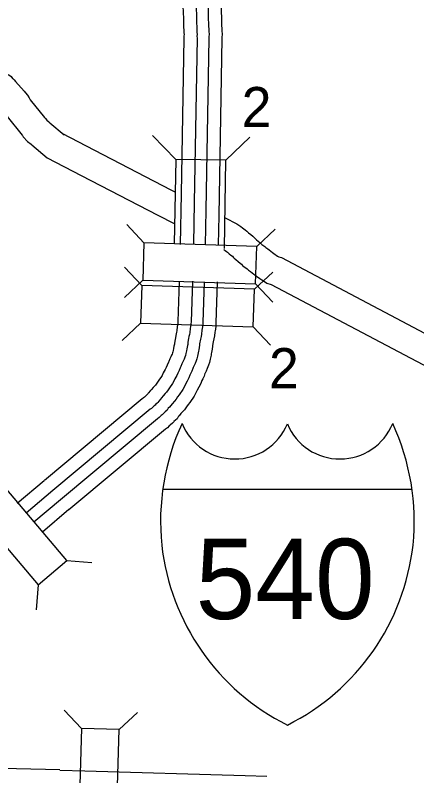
# Model space of a CAD drawing. Extents: x 535214 to 694517, y 381272 to 484355.
# Drawn here: x 544123 to 546236, y 450462 to 454464 of the extents above; entities that cross this region are included whole.
import ezdxf

# ---------------------------------------------------------------- set-up
doc = ezdxf.new("R2010")
doc.units = 0
for name, color, linetype in [('Level 10', 7, 'Continuous'), ('Level 19', 7, 'Continuous'), ('Level 20', 7, 'Continuous'), ('Level 23', 7, 'Continuous')]:
    doc.layers.add(name, color=color, linetype=linetype)

msp = doc.modelspace()

# ---------------------------------------------------------------- linework, layer by layer
at = {"layer": 'Level 10'}
for points in [[(543746.1, 454249.1), (543751.1, 454247.6), (543755.7, 454246.3), (544048.3, 454165.2), (544064.2, 454163.4), (544081.3, 454155), (544089.7, 454150.1), (544101.9, 454141.2), (544109.7, 454131.9), (544110.5, 454131), (544118, 454123.7), (544124.4, 454115.6), (544171.2, 454064.1), (544177.7, 454055.6), (544187.3, 454043.2), (544196.4, 454028.9), (544202.3, 454019.9), (544277.6, 453926.2), (544282.3, 453920.1), (544289.2, 453912), (544301, 453903), (544302, 453901.6), (544306.2, 453898.2), (544381.7, 453834.2)], [(543704.5, 454105), (543709.5, 454103.5), (543714.9, 454102), (544007.8, 454020.8), (544056, 453967.8), (544058.7, 453964.4), (544064.3, 453957), (544070.5, 453947.4), (544080.8, 453931.6), (544159.6, 453833.6), (544161.7, 453830.9), (544165.8, 453824.5), (544188.5, 453799.1), (544207.3, 453785.3), (544210.8, 453782.4), (544291, 453714.4)], [(544368, 453843.5), (544539.6, 453753.5), (544942.2, 453546), (544963.9, 453534.7)], [(544291, 453714.4), (544470.4, 453620.4), (544873.3, 453412.8), (544959.9, 453367.9)], [(545227.2, 453398.2), (545289.4, 453365.9), (545310.2, 453352.1), (545318.9, 453345.6), (545325.6, 453340.4), (545332.5, 453335.3), (545341.3, 453328.2), (545347, 453323), (545350.9, 453319.9), (545363.4, 453310.6), (545373.2, 453301), (545380.7, 453294.2), (545387.7, 453286.9), (545392.8, 453282.5), (545400.8, 453275.9), (545411, 453267.7), (545419.8, 453259.6), (545421.2, 453258.4), (545426.7, 453254.6), (545436.1, 453247.1), (545442.7, 453242), (545451.9, 453234.9), (545459.2, 453229.4), (545468.6, 453222.7), (545477.6, 453215.8), (545484.8, 453210), (545490.4, 453206), (545495.5, 453202.3), (545503.2, 453197.3), (545509.9, 453192.8), (545524.5, 453189.1), (546880.8, 452472.1)], [(545221.7, 453230.8), (545223.5, 453229.6), (545227.9, 453226.3), (545235.3, 453220.6), (545240.5, 453216.8), (545243.8, 453214.1), (545249.2, 453209.3), (545258.4, 453201.6), (545266, 453196.1), (545270.3, 453191.8), (545276, 453186.7), (545284.1, 453178.2), (545296.2, 453167.7), (545306.2, 453159.5), (545313.2, 453153.9), (545319.5, 453148.1), (545328.2, 453140.4), (545336.8, 453134.4), (545343.5, 453129), (545351, 453123.3), (545361, 453115.6), (545370.8, 453108.2), (545379.5, 453102), (545384.6, 453098.1), (545394.5, 453090.1), (545403, 453084.2), (545410, 453079), (545420.4, 453072.2), (545429, 453066.5), (545446.7, 453054.1), (545470.3, 453048.1), (546809.1, 452340.3)], [(543520.6, 450514.2), (544358, 450496.3)], [(544358.8, 450492.6), (544489.3, 450488.9), (545332.6, 450464), (545447.6, 450459.6)]]:
    msp.add_lwpolyline(points, dxfattribs=at)
at = {"layer": 'Level 19'}
for points in [[(544977.4, 454781.7), (544993, 454627.4), (544997.1, 454585.7), (545000.2, 454562.7), (545003.3, 454543), (545004.3, 454526), (545006, 454504.6), (545006.6, 454486.6), (545007.7, 454469.9), (545007.9, 454455.2), (545008.1, 454437.7), (545008.8, 454419.3), (545009.5, 454402.2), (545010.2, 454385.6), (545010.9, 454371.2), (545011.5, 454363.5), (545010.9, 454356.4), (545011.1, 454343.1), (544996.5, 453524.4)], [(545045.8, 454788.6), (545061.4, 454634.2), (545065.4, 454593.6), (545068.2, 454572.7), (545071.8, 454550.4), (545072.9, 454530.7), (545074.6, 454508.5), (545075.3, 454490.2), (545076.5, 454472.6), (545076.6, 454455.9), (545076.8, 454439.5), (545077.5, 454422), (545078.2, 454404.9), (545078.9, 454388.8), (545079.5, 454375.7), (545080.5, 454363.3), (545079.7, 454353.8), (545079.8, 454342.8), (545064.5, 453479.4)], [(545108, 454794.9), (545123.6, 454640.3), (545127.5, 454600.9), (545130.1, 454581.8), (545134, 454557.1), (545135.3, 454534.9), (545137, 454512.1), (545137.7, 454493.4), (545139, 454475), (545139.1, 454456.6), (545139.3, 454441), (545140, 454424.5), (545140.6, 454407.5), (545141.3, 454391.6), (545141.9, 454379.7), (545143.2, 454363.1), (545142.2, 454351.5), (545142.3, 454342.6), (545126.3, 453438.2)], [(545176.4, 454801.8), (545192, 454647.1), (545195.8, 454608.8), (545198.1, 454591.8), (545202.4, 454564.6), (545203.9, 454539.5), (545205.7, 454516), (545206.4, 454496.9), (545207.7, 454477.6), (545207.9, 454457.3), (545208, 454442.7), (545208.7, 454427.2), (545209.3, 454410.3), (545210, 454394.8), (545210.5, 454384.2), (545212.2, 454362.9), (545211, 454349), (545211.1, 454342.3), (545194.5, 453410.3)], [(544996.5, 453524.4), (544991.8, 453258.2)], [(545064.5, 453479.4), (545060.6, 453260.1)], [(545126.3, 453438.2), (545123, 453256)], [(545194.5, 453410.3), (545191.8, 453256.1)], [(544986.6, 453063.2), (544979.7, 452852.5), (544979.6, 452848), (544979.3, 452846.4), (544978.1, 452839.5), (544975.6, 452826.3), (544973.2, 452804.5), (544971.9, 452796.8), (544970.3, 452788.4), (544967.8, 452778.3), (544965.8, 452766.9), (544962.7, 452749.9), (544962.2, 452737.4), (544962, 452735.9), (544961.5, 452733.4), (544958.6, 452722.4), (544956.9, 452710.5), (544954.6, 452699.8), (544953.1, 452693.8), (544951.3, 452688.6), (544948.8, 452681.5), (544946.1, 452675.9), (544941.7, 452666.3), (544936.8, 452656.2), (544932, 452642.6), (544929.9, 452638.5), (544922.8, 452623.8), (544917.2, 452610.3), (544912.5, 452601), (544902.5, 452583.1), (544895.9, 452569.1), (544892.5, 452562.5), (544879.3, 452543.3), (544872, 452533.6), (544864.2, 452522.7), (544860.7, 452518.2), (544848.9, 452505.6), (544840, 452494.2), (544835.9, 452489.3), (544823.6, 452475.9), (544820.9, 452471.6), (544814, 452465.2), (544811.3, 452462.1), (544803.5, 452455.1), (544798.5, 452450.5), (544797.1, 452449.2), (544791.5, 452445.3), (544276.9, 452015.7)], [(545055.5, 453065.2), (545048.4, 452850.2), (545048.1, 452841.2), (545047.1, 452834.8), (545045.7, 452827.2), (545043.6, 452816.1), (545041.3, 452795.2), (545039.6, 452784.9), (545037.5, 452773.6), (545035.1, 452763.9), (545033.5, 452754.8), (545031.2, 452742.3), (545030.7, 452732.2), (545030.1, 452725.9), (545028.6, 452718.2), (545026.1, 452708.5), (545024.5, 452698.3), (545021.5, 452684.2), (545019.1, 452674.4), (545016.2, 452665.9), (545012.4, 452655.4), (545008.6, 452647.1), (545003.8, 452636.8), (545000.3, 452629.5), (544995.4, 452616), (544991.8, 452608.4), (544985.5, 452595.5), (544979.7, 452581.7), (544973.2, 452568.7), (544963.7, 452551.7), (544957.6, 452538.7), (544951.5, 452526.9), (544935.2, 452503.3), (544927.5, 452493), (544919.3, 452481.6), (544913.1, 452473.6), (544901.3, 452461), (544893.4, 452450.8), (544887.4, 452443.7), (544878.4, 452434), (544874, 452426.9), (544870.1, 452423.5), (544863.2, 452417.1), (544858.8, 452412.2), (544854.7, 452408.7), (544849.7, 452404.2), (544845.1, 452400), (544840.6, 452395.7), (544833.4, 452390.7), (544320.9, 451962.9)], [(545117.9, 453061.2), (545110.9, 452848), (545110.4, 452835), (545108.7, 452824.3), (545107.2, 452815.9), (545105.5, 452806.9), (545103.2, 452786.7), (545101.2, 452774), (545098.6, 452760.2), (545096.2, 452750.8), (545095, 452743.9), (545093.5, 452735.3), (545093.1, 452727.4), (545092, 452716.7), (545089.6, 452704.3), (545087.4, 452695.9), (545086.1, 452687.2), (545082.4, 452670.1), (545079.1, 452656.8), (545075.2, 452645.3), (545070.3, 452631.7), (545065.3, 452620.9), (545060.3, 452610), (545058, 452605.2), (545053.1, 452591.7), (545048, 452581.1), (545042.5, 452569.9), (545036.6, 452555.6), (545028.4, 452539.4), (545019.3, 452523.2), (545013.7, 452511), (545005.1, 452494.6), (544986, 452466.9), (544977.9, 452456), (544969.4, 452444.2), (544960.8, 452433), (544948.9, 452420.4), (544941.9, 452411.4), (544934.2, 452402.3), (544928.3, 452395.9), (544922, 452385.9), (544912, 452377.1), (544908, 452373.4), (544902.5, 452367.2), (544895.8, 452361.6), (544891.8, 452357.9), (544887.5, 452354.1), (544880.1, 452347.2), (544871.5, 452341.1), (544361, 451914.9)], [(545186.7, 453061.1), (545179.6, 452845.7), (545179, 452828.1), (545176.4, 452812.7), (545174.8, 452803.6), (545173.5, 452796.7), (545171.4, 452777.4), (545168.9, 452762.1), (545165.7, 452745.4), (545163.5, 452736.5), (545162.7, 452731.8), (545161.9, 452727.7), (545161.7, 452722.2), (545160, 452706.7), (545156.7, 452689.1), (545154.8, 452682), (545153.8, 452674.9), (545149.4, 452654.6), (545145.2, 452637.5), (545140.1, 452622.5), (545133.9, 452605.5), (545127.7, 452592.1), (545122.4, 452580.6), (545121.4, 452578.6), (545116.6, 452565), (545109.8, 452551), (545105.2, 452541.6), (545099.1, 452526.9), (545089.1, 452507.1), (545080.5, 452491.8), (545075.3, 452480.6), (545064.1, 452459.1), (545041.9, 452426.8), (545033.3, 452415.4), (545024.5, 452403.1), (545013.2, 452388.4), (545001.3, 452375.8), (544995.3, 452368), (544985.7, 452356.7), (544983.1, 452354), (544974.8, 452340.7), (544958.1, 452326.1), (544957.2, 452325.2), (544950.5, 452317.7), (544941, 452309.7), (544938, 452307.1), (544934.1, 452303.5), (544923.7, 452293.7), (544913.4, 452286.5), (544405, 451862.1)], [(544276.3, 452015.2), (544134.3, 451894.7)], [(544320.7, 451962.7), (544181, 451844.2)], [(544361.2, 451915.1), (544222, 451797.1)], [(544405.6, 451862.7), (544266.5, 451744.6)]]:
    msp.add_lwpolyline(points, dxfattribs=at)
at = {"layer": 'Level 20'}
for p, q in [((544968.3, 453705.8), (544846.3, 453832.2)), ((545231.8, 453701.1), (545358.2, 453823.1)), ((544968.3, 453705.8), (544960.5, 453262.1)), ((545231.8, 453701.1), (544968.3, 453705.8)), ((545223.6, 453236), (545231.8, 453701.1)), ((544800.8, 453267.5), (544710.6, 453363.8)), ((545394.5, 453248), (545490.9, 453338.2)), ((544788.8, 453041.6), (544698.6, 453138)), ((545382.5, 453022.1), (545478.9, 453112.3)), ((544794.3, 453069.6), (544698, 452979.4)), ((545388, 453050.1), (545478.3, 452953.8)), ((544782.3, 452843.7), (544686, 452753.5)), ((545376, 452824.2), (545466.2, 452727.9)), ((544394.9, 451595.2), (544526.4, 451584.4)), ((544243.9, 451467.1), (544233.1, 451335.5)), ((544471.9, 450711.6), (544381.4, 450807.6)), ((544669.8, 450705.7), (544765.9, 450796.2))]:
    msp.add_line(p, q, dxfattribs=at)
for points in [[(545394.5, 453248), (544800.8, 453267.5), (544794.3, 453069.6), (545388, 453050.1)], [(545382.5, 453022.1), (544788.8, 453041.6), (544782.3, 452843.7), (545376, 452824.2)], [(544394.9, 451595.2), (544010.6, 452048.1), (543859.6, 451920.1), (544243.9, 451467.1)], [(544652.3, 450112), (544669.8, 450705.7), (544471.9, 450711.6), (544454.4, 450117.8)]]:
    msp.add_lwpolyline(points, close=True, dxfattribs=at)
at = {"layer": 'Level 23'}
msp.add_line((544899.8, 451971.3), (546210.7, 451971.3), dxfattribs=at)
for centre, radius, start, end in [((546118, 451800.5), 1230.1, 155.2204, 185.7928), ((545278.7, 452429), 299.7, 202.1459, 337.3414), ((545831.8, 452429), 299.7, 202.6586, 337.8541), ((544992.5, 451800.5), 1230.1, 354.2072, 24.7796), ((546095.4, 451810.9), 1208.7, 186.3923, 243.4571), ((545015.1, 451810.9), 1208.7, 296.5429, 353.6077)]:
    msp.add_arc(centre, radius, start, end, dxfattribs=at)

# ---------------------------------------------------------------- texts
at = {"layer": 'Level 20'}
for p in [(545314.7, 453875.4), (545458.5, 452501.7)]:
    msp.add_text('2', height=211.2, dxfattribs=at).set_placement(p)
at = {"layer": 'Level 23'}
msp.add_text('540', height=422.4, dxfattribs=at).set_placement((545072.2, 451287.3))

doc.saveas('drawing.dxf')
